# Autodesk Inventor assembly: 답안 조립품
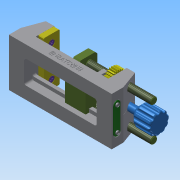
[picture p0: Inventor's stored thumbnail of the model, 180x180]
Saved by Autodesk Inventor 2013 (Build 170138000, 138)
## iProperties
Created: 2017-04
Part Number: 답안 조립품
Document SubType Name: Assembly
Designer: 나래
Author: 나래
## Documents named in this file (10)
- C:\Users\나래\Desktop\370408V1020\답안 조립품.iam
- C:\Users\나래\Desktop\370408V1020\바이스본체 A.ipt
- C:\Users\나래\Desktop\370408V1020\고정 플레이트.ipt
- C:\Users\나래\Desktop\370408V1020\바이스본체 B.ipt
- C:\Users\나래\Desktop\370408V1020\스퍼기어.ipt
- C:\Users\나래\Desktop\370408V1020\슬라이딩 부품.ipt
- C:\Users\나래\Desktop\370408V1020\십자오목머리나사 M3.ipt
- C:\Users\나래\Desktop\370408V1020\십자오목머리나사 M4.ipt
- C:\Users\나래\Desktop\370408V1020\지지대.ipt
- C:\Users\나래\Desktop\370408V1020\핸들.ipt
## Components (3 placed, 2 different names)
1. 고정 플레이트:1
2. 핸들:1 — 플러쉬:2, 각도:1
3. 고정 플레이트:2
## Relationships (2: Flush 1, Angle 1)
- 플러쉬:2 [Flush]: 핸들:1
- 각도:1 [Angle]: 핸들:1
